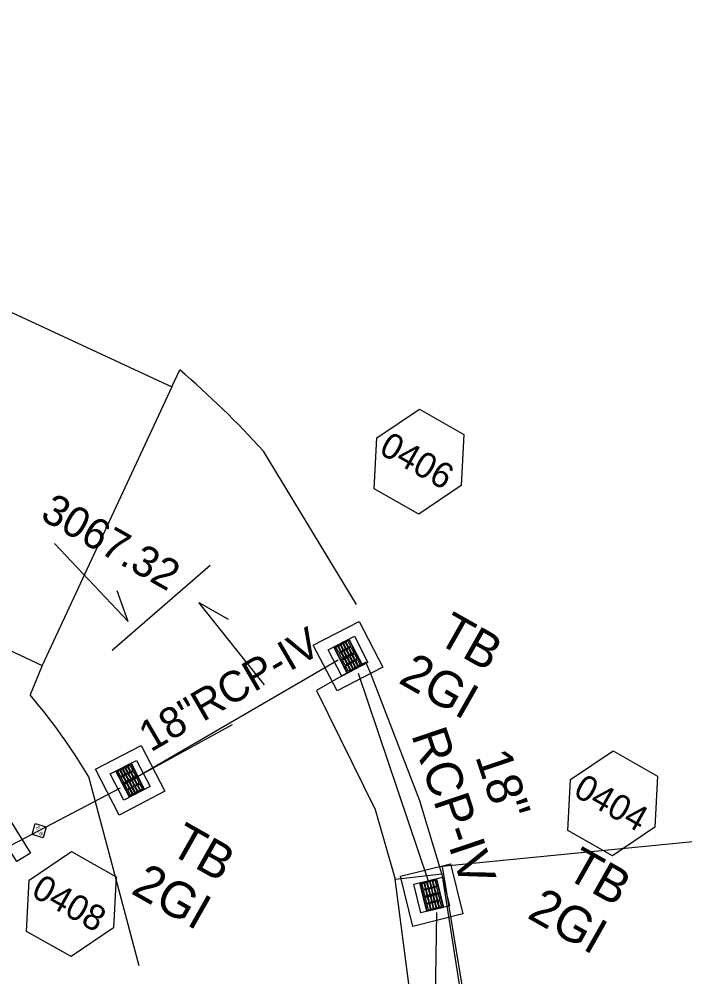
# Model space of a CAD drawing. Extents: x 1116825 to 1117461, y 843538 to 843929.
# Drawn here: x 1116969.1 to 1117034.1, y 843703.9 to 843797.5 of the extents above; entities that cross this region are included whole.
import ezdxf

# ---------------------------------------------------------------- set-up
doc = ezdxf.new("R2010")
doc.units = 0
for name, color, linetype in [('Exist Plan Preparation Watershed Blue', 7, 'Continuous'), ('Exist Plan Preparation Watershed Red', 7, 'Continuous'), ('Prop Approach Slab', 7, 'Continuous'), ('Prop Drainage Structure Box Number Symbol CELL', 7, 'Continuous'), ('Prop Drainage Structure Bridge', 7, 'Continuous'), ('Prop Drainage Structure Drop Inlet Grate 2 Wide Slots and Flat Grates 840 20 TB CELL', 7, 'Continuous'), ('Prop Drainage Structure Drop Inlet Grate 2 Wide Slots and Flat Grates 840 20 TB Label', 7, 'Continuous'), ('Prop Drainage Structure Drop Inlet Grate 2 Wide Slots and Sag Grates 840 22 TB CELL', 7, 'Continuous'), ('Prop Drainage Structure Drop Inlet Grate 2 Wide Slots and Sag Grates 840 22 TB Label', 7, 'Continuous'), ('Prop Drainage Structure Pipe CSP Rod and Lug with Sleeve Gaskets CELL', 7, 'Continuous'), ('Prop Drainage Structure Pipe Elbow Alternate CELL', 7, 'Continuous'), ('Prop Drainage Structure Pipe RCP 18in Class IV', 7, 'Continuous'), ('Prop Drainage Structure Pipe RCP 18in Class IV Label', 7, 'Continuous'), ('Prop Drainage Structure Plot Symbol 20 Scale', 7, 'Continuous'), ('Prop Drainage Structure Plot Symbol 50 Scale', 7, 'Continuous'), ('Prop Plan Preparation Sag', 7, 'Continuous'), ('Prop SS Fill Line', 7, 'Continuous')]:
    doc.layers.add(name, color=color, linetype=linetype)

msp = doc.modelspace()

# ---------------------------------------------------------------- linework, layer by layer
at = {"layer": 'Exist Plan Preparation Watershed Blue'}
msp.add_line((1116979.193, 843722.696), (1116989.928, 843728.578), dxfattribs=at)
for points in [[(1117002.956, 843734.66), (1116998.153, 843731.91), (1117003.88, 843720.295), (1117005.836, 843713.488), (1117010.389, 843713.986), (1117008.226, 843721.14), (1117003.413, 843733.63)], [(1117011.885, 843658.685), (1116996.777, 843656.938), (1116997.383, 843668.372), (1116999.37, 843683.653), (1117007.834, 843698.002), (1117005.836, 843713.488), (1117010.389, 843713.986), (1117012.546, 843700.29), (1117012.982, 843688.081), (1117011.698, 843672.231)]]:
    msp.add_lwpolyline(points, close=True, dxfattribs=at)
at = {"layer": 'Exist Plan Preparation Watershed Red'}
msp.add_lwpolyline([(1117010.411, 843714.718), (1117013.742, 843694.706), (1117013.849, 843667.871), (1117011.885, 843658.685), (1116996.777, 843656.938), (1116999.948, 843633.959), (1117011.908, 843596.884), (1117025.614, 843575.885), (1117048.706, 843550.163), (1117064.026, 843538.254), (1117084.772, 843547.622), (1117217.346, 843572.439), (1117328.842, 843554.913), (1117432.926, 843571.688), (1117450.498, 843607.653), (1117450.734, 843646.266), (1117460.848, 843746.894), (1117431.963, 843772.255), (1117401.493, 843797.454), (1117287.628, 843757.831), (1117159.594, 843729.383)], close=True, dxfattribs=at)
at = {"layer": 'Prop Approach Slab'}
for radius, start, end in [(93.118, 42.35326, 49.37756), (60.281, 30.85991, 40.21716)]:
    msp.add_arc((1116924.154, 843692.54), radius, start, end, dxfattribs=at)
at = {"layer": 'Prop Drainage Structure Box Number Symbol CELL'}
for points in [[(1117008.193, 843759.372), (1117012.544, 843756.909), (1117012.287, 843751.916), (1117008.138, 843749.126), (1117003.787, 843751.589), (1117004.044, 843756.582), (1117008.193, 843759.372)], [(1117027.11, 843726.001), (1117031.461, 843723.538), (1117031.204, 843718.544), (1117027.055, 843715.754), (1117022.704, 843718.217), (1117022.961, 843723.21), (1117027.11, 843726.001)], [(1116974.224, 843716.167), (1116978.576, 843713.704), (1116978.319, 843708.711), (1116974.17, 843705.92), (1116969.818, 843708.383), (1116970.075, 843713.376), (1116974.224, 843716.167)]]:
    msp.add_lwpolyline(points, dxfattribs=at)
at = {"layer": 'Prop Drainage Structure Bridge'}
for p, q in [((1116938.666, 843782.63), (1116984.005, 843761.551)), ((1116984.005, 843761.551), (1116984.78, 843763.218)), ((1116984.005, 843761.551), (1116971.357, 843734.347)), ((1116926.018, 843755.427), (1116971.357, 843734.347)), ((1116971.357, 843734.347), (1116970.184, 843731.462))]:
    msp.add_line(p, q, dxfattribs=at)
at = {"layer": 'Prop Drainage Structure Drop Inlet Grate 2 Wide Slots and Flat Grates 840 20 TB CELL'}
for p, q in [((1117000.567, 843736.529), (1117000.567, 843736.529)), ((1117001.231, 843735.251), (1117001.231, 843735.251)), ((1117001.976, 843735.638), (1117001.976, 843735.638)), ((1117000.485, 843734.864), (1117000.485, 843734.864)), ((1117001.894, 843733.973), (1117001.894, 843733.973)), ((1116979.282, 843724.414), (1116979.282, 843724.414)), ((1116979.945, 843723.135), (1116979.945, 843723.135)), ((1116980.691, 843723.522), (1116980.691, 843723.522)), ((1116979.199, 843722.748), (1116979.199, 843722.748)), ((1116980.608, 843721.857), (1116980.608, 843721.857))]:
    msp.add_line(p, q, dxfattribs=at)
for points in [[(1117001.313, 843736.916), (1117002.64, 843734.36), (1117001.148, 843733.586), (1116999.822, 843736.142), (1117001.313, 843736.916)], [(1117001.294, 843736.855), (1117002.579, 843734.379), (1117001.168, 843733.647), (1116999.883, 843736.123), (1117001.294, 843736.855)], [(1117001.291, 843736.845), (1117001.926, 843735.62), (1117000.528, 843734.895), (1116999.893, 843736.12), (1117001.291, 843736.845)], [(1117000.213, 843736.219), (1117000.489, 843735.686), (1117000.316, 843735.596), (1117000.04, 843736.129), (1117000.213, 843736.219)], [(1117000.459, 843736.346), (1117000.736, 843735.814), (1117000.563, 843735.724), (1117000.286, 843736.257), (1117000.459, 843736.346)], [(1117000.706, 843736.474), (1117000.982, 843735.942), (1117000.809, 843735.852), (1117000.533, 843736.384), (1117000.706, 843736.474)], [(1117000.952, 843736.602), (1117001.228, 843736.069), (1117001.055, 843735.98), (1117000.779, 843736.512), (1117000.952, 843736.602)], [(1117001.198, 843736.73), (1117001.475, 843736.197), (1117001.302, 843736.107), (1117001.025, 843736.64), (1117001.198, 843736.73)], [(1117001.256, 843736.016), (1117001.532, 843735.484), (1117001.359, 843735.394), (1117001.083, 843735.926), (1117001.256, 843736.016)], [(1117001.502, 843736.144), (1117001.779, 843735.611), (1117001.606, 843735.522), (1117001.329, 843736.054), (1117001.502, 843736.144)], [(1117000.517, 843735.633), (1117000.793, 843735.1), (1117000.62, 843735.01), (1117000.344, 843735.543), (1117000.517, 843735.633)], [(1117001.933, 843735.607), (1117002.569, 843734.382), (1117001.171, 843733.657), (1117000.535, 843734.882), (1117001.933, 843735.607)], [(1117000.763, 843735.761), (1117001.04, 843735.228), (1117000.867, 843735.138), (1117000.59, 843735.671), (1117000.763, 843735.761)], [(1117000.856, 843734.98), (1117001.132, 843734.448), (1117000.959, 843734.358), (1117000.683, 843734.89), (1117000.856, 843734.98)], [(1117001.01, 843735.888), (1117001.286, 843735.356), (1117001.113, 843735.266), (1117000.837, 843735.799), (1117001.01, 843735.888)], [(1117001.102, 843735.108), (1117001.378, 843734.576), (1117001.205, 843734.486), (1117000.929, 843735.018), (1117001.102, 843735.108)], [(1117001.348, 843735.236), (1117001.625, 843734.703), (1117001.452, 843734.614), (1117001.175, 843735.146), (1117001.348, 843735.236)], [(1117001.595, 843735.364), (1117001.871, 843734.831), (1117001.698, 843734.741), (1117001.422, 843735.274), (1117001.595, 843735.364)], [(1117001.595, 843735.364), (1117001.871, 843734.831), (1117001.698, 843734.741), (1117001.422, 843735.274), (1117001.595, 843735.364)], [(1117001.841, 843735.492), (1117002.117, 843734.959), (1117001.944, 843734.869), (1117001.668, 843735.402), (1117001.841, 843735.492)], [(1117001.16, 843734.395), (1117001.436, 843733.862), (1117001.263, 843733.772), (1117000.987, 843734.305), (1117001.16, 843734.395)], [(1117001.406, 843734.522), (1117001.682, 843733.99), (1117001.509, 843733.9), (1117001.233, 843734.433), (1117001.406, 843734.522)], [(1117001.652, 843734.65), (1117001.929, 843734.118), (1117001.756, 843734.028), (1117001.479, 843734.56), (1117001.652, 843734.65)], [(1117001.899, 843734.778), (1117002.175, 843734.245), (1117002.002, 843734.156), (1117001.726, 843734.688), (1117001.899, 843734.778)], [(1117001.899, 843734.778), (1117002.175, 843734.245), (1117002.002, 843734.156), (1117001.726, 843734.688), (1117001.899, 843734.778)], [(1117002.145, 843734.906), (1117002.421, 843734.373), (1117002.248, 843734.283), (1117001.972, 843734.816), (1117002.145, 843734.906)], [(1116980.027, 843724.8), (1116981.354, 843722.244), (1116979.863, 843721.47), (1116978.536, 843724.027), (1116980.027, 843724.8)], [(1116980.008, 843724.74), (1116981.293, 843722.263), (1116979.882, 843721.531), (1116978.597, 843724.007), (1116980.008, 843724.74)], [(1116980.005, 843724.73), (1116980.641, 843723.505), (1116979.243, 843722.779), (1116978.607, 843724.004), (1116980.005, 843724.73)], [(1116978.927, 843724.103), (1116979.204, 843723.57), (1116979.031, 843723.481), (1116978.754, 843724.013), (1116978.927, 843724.103)], [(1116979.174, 843724.231), (1116979.45, 843723.698), (1116979.277, 843723.608), (1116979.001, 843724.141), (1116979.174, 843724.231)], [(1116979.42, 843724.359), (1116979.696, 843723.826), (1116979.523, 843723.736), (1116979.247, 843724.269), (1116979.42, 843724.359)], [(1116979.666, 843724.486), (1116979.943, 843723.954), (1116979.77, 843723.864), (1116979.493, 843724.397), (1116979.666, 843724.486)], [(1116979.724, 843723.773), (1116980, 843723.24), (1116979.827, 843723.15), (1116979.551, 843723.683), (1116979.724, 843723.773)], [(1116979.913, 843724.614), (1116980.189, 843724.082), (1116980.016, 843723.992), (1116979.74, 843724.524), (1116979.913, 843724.614)], [(1116979.97, 843723.901), (1116980.247, 843723.368), (1116980.074, 843723.278), (1116979.797, 843723.811), (1116979.97, 843723.901)], [(1116980.217, 843724.028), (1116980.493, 843723.496), (1116980.32, 843723.406), (1116980.044, 843723.939), (1116980.217, 843724.028)], [(1116979.231, 843723.517), (1116979.508, 843722.985), (1116979.335, 843722.895), (1116979.058, 843723.427), (1116979.231, 843723.517)], [(1116980.647, 843723.491), (1116981.283, 843722.267), (1116979.885, 843721.541), (1116979.249, 843722.766), (1116980.647, 843723.491)], [(1116979.478, 843723.645), (1116979.754, 843723.112), (1116979.581, 843723.023), (1116979.305, 843723.555), (1116979.478, 843723.645)], [(1116979.57, 843722.865), (1116979.846, 843722.332), (1116979.673, 843722.242), (1116979.397, 843722.775), (1116979.57, 843722.865)], [(1116979.816, 843722.993), (1116980.093, 843722.46), (1116979.92, 843722.37), (1116979.643, 843722.903), (1116979.816, 843722.993)], [(1116980.063, 843723.12), (1116980.339, 843722.588), (1116980.166, 843722.498), (1116979.89, 843723.031), (1116980.063, 843723.12)], [(1116980.309, 843723.248), (1116980.585, 843722.716), (1116980.412, 843722.626), (1116980.136, 843723.158), (1116980.309, 843723.248)], [(1116980.309, 843723.248), (1116980.585, 843722.716), (1116980.412, 843722.626), (1116980.136, 843723.158), (1116980.309, 843723.248)], [(1116980.555, 843723.376), (1116980.832, 843722.844), (1116980.659, 843722.754), (1116980.382, 843723.286), (1116980.555, 843723.376)], [(1116979.874, 843722.279), (1116980.15, 843721.746), (1116979.977, 843721.657), (1116979.701, 843722.189), (1116979.874, 843722.279)], [(1116980.12, 843722.407), (1116980.397, 843721.874), (1116980.224, 843721.784), (1116979.947, 843722.317), (1116980.12, 843722.407)], [(1116980.367, 843722.535), (1116980.643, 843722.002), (1116980.47, 843721.912), (1116980.194, 843722.445), (1116980.367, 843722.535)], [(1116980.613, 843722.662), (1116980.889, 843722.13), (1116980.716, 843722.04), (1116980.44, 843722.573), (1116980.613, 843722.662)], [(1116980.613, 843722.662), (1116980.889, 843722.13), (1116980.716, 843722.04), (1116980.44, 843722.573), (1116980.613, 843722.662)], [(1116980.859, 843722.79), (1116981.136, 843722.258), (1116980.963, 843722.168), (1116980.686, 843722.7), (1116980.859, 843722.79)]]:
    msp.add_lwpolyline(points, dxfattribs=at)
at = {"layer": 'Prop Drainage Structure Drop Inlet Grate 2 Wide Slots and Sag Grates 840 22 TB CELL'}
for p, q in [((1117009.048, 843713.321), (1117009.048, 843713.321)), ((1117008.579, 843711.721), (1117008.579, 843711.721)), ((1117009.394, 843711.923), (1117009.394, 843711.923)), ((1117010.21, 843712.125), (1117010.21, 843712.125)), ((1117009.74, 843710.525), (1117009.74, 843710.525))]:
    msp.add_line(p, q, dxfattribs=at)
for points in [[(1117009.863, 843713.523), (1117010.556, 843710.727), (1117008.925, 843710.323), (1117008.233, 843713.119), (1117009.863, 843713.523)], [(1117009.83, 843713.468), (1117010.501, 843710.76), (1117008.958, 843710.378), (1117008.287, 843713.086), (1117009.83, 843713.468), (1117009.83, 843713.468)], [(1117009.825, 843713.459), (1117010.157, 843712.12), (1117008.628, 843711.741), (1117008.296, 843713.08), (1117009.825, 843713.459)], [(1117008.631, 843713.101), (1117008.775, 843712.519), (1117008.586, 843712.472), (1117008.442, 843713.055), (1117008.631, 843713.101)], [(1117008.9, 843713.168), (1117009.045, 843712.586), (1117008.855, 843712.539), (1117008.711, 843713.121), (1117008.9, 843713.168)], [(1117009.17, 843713.235), (1117009.314, 843712.653), (1117009.125, 843712.606), (1117008.98, 843713.188), (1117009.17, 843713.235)], [(1117009.328, 843712.594), (1117009.473, 843712.012), (1117009.283, 843711.965), (1117009.139, 843712.547), (1117009.328, 843712.594)], [(1117009.439, 843713.302), (1117009.583, 843712.719), (1117009.394, 843712.672), (1117009.25, 843713.255), (1117009.439, 843713.302)], [(1117009.598, 843712.661), (1117009.742, 843712.079), (1117009.553, 843712.032), (1117009.408, 843712.614), (1117009.598, 843712.661)], [(1117009.708, 843713.368), (1117009.853, 843712.786), (1117009.663, 843712.739), (1117009.519, 843713.322), (1117009.708, 843713.368)], [(1117009.867, 843712.728), (1117010.011, 843712.145), (1117009.822, 843712.098), (1117009.678, 843712.681), (1117009.867, 843712.728)], [(1117008.79, 843712.461), (1117008.934, 843711.878), (1117008.745, 843711.832), (1117008.6, 843712.414), (1117008.79, 843712.461)], [(1117010.16, 843712.105), (1117010.492, 843710.765), (1117008.963, 843710.387), (1117008.632, 843711.726), (1117010.16, 843712.105)], [(1117008.966, 843711.747), (1117009.111, 843711.165), (1117008.921, 843711.118), (1117008.777, 843711.701), (1117008.966, 843711.747)], [(1117009.059, 843712.528), (1117009.203, 843711.945), (1117009.014, 843711.898), (1117008.87, 843712.481), (1117009.059, 843712.528)], [(1117009.236, 843711.814), (1117009.38, 843711.232), (1117009.191, 843711.185), (1117009.047, 843711.767), (1117009.236, 843711.814)], [(1117009.505, 843711.881), (1117009.649, 843711.298), (1117009.46, 843711.252), (1117009.316, 843711.834), (1117009.505, 843711.881)], [(1117009.774, 843711.948), (1117009.919, 843711.365), (1117009.729, 843711.318), (1117009.585, 843711.901), (1117009.774, 843711.948)], [(1117010.044, 843712.014), (1117010.188, 843711.432), (1117009.999, 843711.385), (1117009.855, 843711.967), (1117010.044, 843712.014)], [(1117009.125, 843711.107), (1117009.269, 843710.524), (1117009.08, 843710.477), (1117008.936, 843711.06), (1117009.125, 843711.107)], [(1117009.394, 843711.174), (1117009.539, 843710.591), (1117009.349, 843710.544), (1117009.205, 843711.127), (1117009.394, 843711.174)], [(1117009.664, 843711.24), (1117009.808, 843710.658), (1117009.619, 843710.611), (1117009.475, 843711.193), (1117009.664, 843711.24)], [(1117009.933, 843711.307), (1117010.077, 843710.725), (1117009.888, 843710.678), (1117009.744, 843711.26), (1117009.933, 843711.307)], [(1117010.202, 843711.374), (1117010.347, 843710.791), (1117010.158, 843710.744), (1117010.013, 843711.327), (1117010.202, 843711.374)]]:
    msp.add_lwpolyline(points, dxfattribs=at)
at = {"layer": 'Prop Drainage Structure Pipe CSP Rod and Lug with Sleeve Gaskets CELL'}
msp.add_lwpolyline([(1116967.387, 843716.405), (1116967.911, 843716.732), (1116966.95, 843718.271), (1116968.292, 843719.109), (1116970.214, 843716.03), (1116968.872, 843715.192), (1116967.911, 843716.732)], dxfattribs=at)
at = {"layer": 'Prop Drainage Structure Pipe Elbow Alternate CELL'}
msp.add_line((1116971.057, 843718.22), (1116971.057, 843718.22), dxfattribs=at)
msp.add_line((1116971.057, 843718.22), (1116971.057, 843718.22), dxfattribs=at)
msp.add_lwpolyline([(1116970.679, 843718.911), (1116971.748, 843718.597), (1116971.434, 843717.528), (1116970.366, 843717.842), (1116970.679, 843718.911)], dxfattribs=at)
at = {"layer": 'Prop Drainage Structure Pipe RCP 18in Class IV'}
for p, q in [((1117000.259, 843734.858), (1116980.901, 843723.6)), ((1117009.068, 843713.296), (1117002.256, 843733.557)), ((1116978.978, 843722.357), (1116957.744, 843711.232)), ((1117009.127, 843656.655), (1117009.892, 843710.223))]:
    msp.add_line(p, q, dxfattribs=at)
at = {"layer": 'Prop Drainage Structure Plot Symbol 20 Scale'}
for points in [[(1117001.846, 843737.192), (1117003.172, 843734.636), (1117000.616, 843733.309), (1116999.289, 843735.866)], [(1116980.56, 843725.077), (1116981.886, 843722.521), (1116979.33, 843721.194), (1116978.004, 843723.75)], [(1117010.446, 843713.667), (1117011.138, 843710.871), (1117008.343, 843710.179), (1117007.65, 843712.974)]]:
    msp.add_lwpolyline(points, close=True, dxfattribs=at)
at = {"layer": 'Prop Drainage Structure Plot Symbol 50 Scale'}
for points in [[(1117002.307, 843738.648), (1117004.628, 843734.175), (1117000.155, 843731.853), (1116997.833, 843736.327)], [(1116981.021, 843726.533), (1116983.342, 843722.059), (1116978.869, 843719.738), (1116976.548, 843724.211)], [(1117011.234, 843714.975), (1117012.446, 843710.083), (1117007.554, 843708.871), (1117006.342, 843713.763)]]:
    msp.add_lwpolyline(points, close=True, dxfattribs=at)
at = {"layer": 'Prop Plan Preparation Sag'}
msp.add_line((1116987.758, 843744.112), (1116978.184, 843735.812), dxfattribs=at)
for points in [[(1116972.549, 843746.259), (1116979.755, 843738.626), (1116978.675, 843741.639)], [(1116993.061, 843732.439), (1116986.663, 843740.48), (1116989.5, 843738.874)]]:
    msp.add_lwpolyline(points, dxfattribs=at)
at = {"layer": 'Prop SS Fill Line'}
for p, q in [((1117002.039, 843740.304), (1116992.968, 843755.274)), ((1116980.818, 843705.019), (1116975.9, 843723.46))]:
    msp.add_line(p, q, dxfattribs=at)

# ---------------------------------------------------------------- texts
at = {"layer": 'Prop Drainage Structure Box Number Symbol CELL'}
for s, p in [('0406', (1117004.13, 843755.097)), ('0404', (1117023.101, 843721.695)), ('0408', (1116970.157, 843711.894))]:
    msp.add_text(s, height=2.5, rotation=330.48854, dxfattribs=at).set_placement(p)
at = {"layer": 'Prop Drainage Structure Drop Inlet Grate 2 Wide Slots and Flat Grates 840 20 TB Label'}
for s, p in [('TB', (1117009.738, 843736.64)), ('2GI', (1117006.03, 843732.706)), ('TB', (1116983.616, 843716.081)), ('2GI', (1116979.909, 843712.147))]:
    msp.add_text(s, height=3.5, rotation=330.48854, dxfattribs=at).set_placement(p)
at = {"layer": 'Prop Drainage Structure Drop Inlet Grate 2 Wide Slots and Sag Grates 840 22 TB Label'}
for s, p in [('TB', (1117022.311, 843713.698)), ('2GI', (1117018.603, 843709.764))]:
    msp.add_text(s, height=3.5, rotation=330.48854, dxfattribs=at).set_placement(p)
at = {"layer": 'Prop Drainage Structure Pipe Elbow Alternate CELL'}
msp.add_text('ELB', height=0.36, rotation=298.62763, dxfattribs=at).set_placement((1116970.721, 843718.521))
at = {"layer": 'Prop Drainage Structure Pipe RCP 18in Class IV Label'}
for s, height, rotation, p in [('18"RCP-IV ', 3, 30.18345, (1116981.948, 843725.834)), ('RCP-IV ', 3.5, 288.58321, (1117007.371, 843727.574)), ('18"', 3.5, 288.58321, (1117013.622, 843725.457))]:
    msp.add_text(s, height=height, rotation=rotation, dxfattribs=at).set_placement(p)
at = {"layer": 'Prop Plan Preparation Sag'}
msp.add_text('3067.32', height=3, rotation=330.48854, dxfattribs=at).set_placement((1116971.04, 843748.684))

doc.saveas('drawing.dxf')
